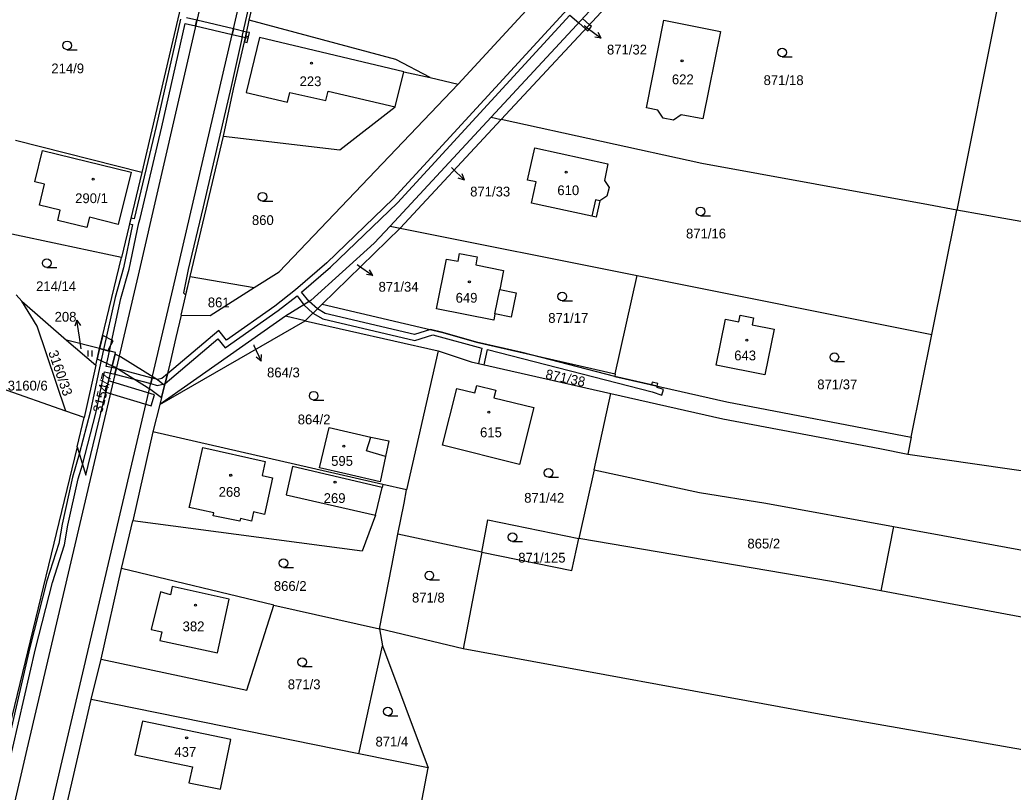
# Model space of a CAD drawing. Extents: x -776734 to -748832, y -1118122 to -976986.
# Drawn here: x -752855.4 to -752682.9, y -1114956.2 to -1114822 of the extents above; entities that cross this region are included whole.
import ezdxf

# ---------------------------------------------------------------- set-up
doc = ezdxf.new("R2010")
doc.units = 0
for name, color, linetype in [('KM_Hranice parcel', 7, 'Continuous'), ('KM_Parcelní čísla', 7, 'Continuous'), ('KM_Pop  PČ popisy', 7, 'Continuous'), ('KM_Vnitřní kresba', 7, 'Continuous'), ('KM_Věcná břemena k části', 7, 'Continuous'), ('KM_Značky budov', 7, 'Continuous'), ('KM_Značky kultur', 7, 'Continuous')]:
    doc.layers.add(name, color=color, linetype=linetype)

msp = doc.modelspace()

# ---------------------------------------------------------------- linework, layer by layer
at = {"layer": 'KM_Hranice parcel'}
for p, q in [((-752815.59, -1114822.06), (-752810.36, -1114800.13)), ((-752743.15, -1114806.14), (-752773.56, -1114838.95)), ((-752741.43, -1114806.72), (-752771.79, -1114839.34)), ((-752826.26, -1114814.37), (-752834.25, -1114848.56)), ((-752779.3, -1114833.2), (-752760.8, -1114813.12)), ((-752685.29, -1114818.2), (-752692.66, -1114855.09)), ((-752810.37, -1114865.82), (-752779.3, -1114833.2)), ((-752784.17, -1114832.03), (-752779.3, -1114833.2)), ((-752773.56, -1114838.95), (-752791.09, -1114857.86)), ((-752771.79, -1114839.34), (-752789.34, -1114858.2)), ((-752773.56, -1114838.95), (-752771.79, -1114839.34)), ((-752834.25, -1114848.56), (-752856.18, -1114842.98)), ((-752825.84, -1114866.6), (-752820.07, -1114842.27)), ((-752834.25, -1114848.56), (-752837.78, -1114863.34)), ((-752697, -1114876.69), (-752692.66, -1114855.09)), ((-752646.6, -1114863.22), (-752692.66, -1114855.09)), ((-752789.34, -1114858.2), (-752802.89, -1114871.42)), ((-752791.09, -1114857.86), (-752789.34, -1114858.2)), ((-752789.34, -1114858.2), (-752748.21, -1114866.44)), ((-752841.58, -1114879.15), (-752837.78, -1114863.34)), ((-752814.71, -1114868.55), (-752810.37, -1114865.82)), ((-752827.44, -1114873.35), (-752825.84, -1114866.6)), ((-752825.84, -1114866.6), (-752814.71, -1114868.55)), ((-752751.98, -1114883.52), (-752748.21, -1114866.44)), ((-752748.21, -1114866.44), (-752697, -1114876.69)), ((-752856.07, -1114869.8), (-752855.1, -1114870.94)), ((-752855.1, -1114870.94), (-752847.34, -1114877.68)), ((-752809.29, -1114873.54), (-752831.11, -1114888.85)), ((-752831.11, -1114888.85), (-752805.86, -1114874.32)), ((-752805.86, -1114874.32), (-752809.29, -1114873.54)), ((-752805.86, -1114874.32), (-752782.75, -1114879.56)), ((-752847.34, -1114877.68), (-752842.23, -1114882.06)), ((-752841.58, -1114879.15), (-752847.34, -1114877.68)), ((-752700.55, -1114894.54), (-752697, -1114876.69)), ((-752842.23, -1114882.06), (-752841.58, -1114879.15)), ((-752782.75, -1114879.56), (-752788.24, -1114903.71)), ((-752782.75, -1114879.56), (-752777.02, -1114881.46)), ((-752777.02, -1114881.46), (-752752.74, -1114886.95)), ((-752842.23, -1114882.06), (-752844.28, -1114891.15)), ((-752847.45, -1114890.03), (-752858.6, -1114886.11)), ((-752755.67, -1114900.22), (-752752.74, -1114886.95)), ((-752844.28, -1114891.15), (-752847.45, -1114890.03)), ((-752831.11, -1114888.85), (-752832.34, -1114893.61)), ((-752845.51, -1114896.23), (-752844.28, -1114891.15)), ((-752832.34, -1114893.61), (-752835.83, -1114909.11)), ((-752792.39, -1114902.76), (-752832.34, -1114893.61)), ((-752700.55, -1114894.54), (-752701.14, -1114897.48)), ((-752845.51, -1114896.23), (-752858.15, -1114948.58)), ((-752755.67, -1114900.22), (-752758.3, -1114912.14)), ((-752793.64, -1114908.09), (-752792.51, -1114903.31)), ((-752792.39, -1114902.76), (-752792.51, -1114903.31)), ((-752788.24, -1114903.71), (-752792.39, -1114902.76)), ((-752788.68, -1114905.99), (-752788.24, -1114903.71)), ((-752789.74, -1114911.43), (-752788.68, -1114905.99)), ((-752725.83, -1114905.99), (-752703.64, -1114910.05)), ((-752837.8, -1114917.4), (-752835.83, -1114909.11)), ((-752703.64, -1114910.05), (-752705.87, -1114921.23)), ((-752703.64, -1114910.05), (-752695.08, -1114911.61)), ((-752790.8, -1114916.88), (-752789.74, -1114911.43)), ((-752775.2, -1114914.55), (-752789.74, -1114911.43)), ((-752714.41, -1114919.62), (-752758.3, -1114912.14)), ((-752841.33, -1114933.1), (-752837.8, -1114917.4)), ((-752811.3, -1114923.77), (-752837.8, -1114917.4)), ((-752792.93, -1114927.88), (-752790.8, -1114916.88)), ((-752705.87, -1114921.23), (-752714.41, -1114919.62)), ((-752625.35, -1114936.43), (-752705.87, -1114921.23)), ((-752811.3, -1114923.77), (-752792.93, -1114927.88)), ((-752778.39, -1114931.34), (-752792.93, -1114927.88)), ((-752792.93, -1114927.88), (-752792.43, -1114930.79)), ((-752796.52, -1114949.56), (-752792.43, -1114930.79)), ((-752792.43, -1114930.79), (-752784.52, -1114951.99)), ((-752843.05, -1114940.12), (-752841.33, -1114933.1)), ((-752848.45, -1114963.61), (-752843.05, -1114940.12)), ((-752796.52, -1114949.56), (-752843.05, -1114940.12)), ((-752784.52, -1114951.99), (-752796.52, -1114949.56)), ((-752787.01, -1114965.1), (-752784.52, -1114951.99))]:
    msp.add_line(p, q, dxfattribs=at)
for points in [[(-752785.56, -1114653.59), (-752802.93, -1114729.01), (-752805.4, -1114739.76), (-752817.12, -1114789.2), (-752834.89, -1114866.39), (-752854.22, -1114948.74), (-752882.92, -1115072.56), (-752893.17, -1115116.65), (-752898.67, -1115140.84), (-752901.21, -1115152.69), (-752902.77, -1115162.03), (-752904.54, -1115175.28), (-752905.59, -1115186.25), (-752907.24, -1115206.15), (-752907.97, -1115217.91), (-752910.76, -1115260.79), (-752912.73, -1115288.36)], [(-752893.27, -1115146.65), (-752892.2, -1115141.48), (-752884.4, -1115107.23), (-752882.98, -1115101.01), (-752882.52, -1115099.06), (-752878.08, -1115079.92), (-752848.33, -1114951.79), (-752828.79, -1114868.65), (-752810.45, -1114789.66), (-752799.15, -1114740.86), (-752796.77, -1114730.63), (-752779.02, -1114654.54)], [(-752820.07, -1114842.27), (-752818.33, -1114834.09), (-752816.08, -1114824.33), (-752815.59, -1114822.06)], [(-752784.17, -1114832.03), (-752790.14, -1114828.93), (-752815.59, -1114822.06)], [(-752746.57, -1114837.3), (-752743.53, -1114822.09), (-752733.73, -1114824.05), (-752736.77, -1114839.24), (-752740.53, -1114838.52), (-752741.89, -1114839.44), (-752743.68, -1114839.12), (-752744.59, -1114837.72), (-752746.57, -1114837.3)], [(-752820.07, -1114842.27), (-752799.84, -1114844.62), (-752790.23, -1114837.17), (-752788.71, -1114831.09), (-752784.17, -1114832.03)], [(-752692.66, -1114855.09), (-752697.57, -1114854.2), (-752736.92, -1114847), (-752771.79, -1114839.34)], [(-752766.54, -1114853.86), (-752765.74, -1114850.2), (-752767.21, -1114849.89), (-752765.97, -1114844.25), (-752753.28, -1114847.03), (-752753.88, -1114849.93), (-752753.07, -1114851.16), (-752753.43, -1114852.65), (-752754.68, -1114853.45), (-752755.3, -1114856.31), (-752756.05, -1114856.15), (-752766.54, -1114853.86)], [(-752837.78, -1114863.34), (-752862.35, -1114858.12), (-752867.05, -1114856.95)], [(-752791.09, -1114857.86), (-752793.86, -1114860.85), (-752804.88, -1114870.79), (-752809.29, -1114873.54)], [(-752776.24, -1114864.59), (-752771.39, -1114865.56), (-752772.05, -1114868.89), (-752769.23, -1114869.45), (-752770.06, -1114873.67), (-752772.89, -1114873.12), (-752773.1, -1114874.19), (-752783.04, -1114872.22), (-752781.3, -1114863.59), (-752779.3, -1114863.99), (-752779.03, -1114862.63), (-752775.97, -1114863.22), (-752776.24, -1114864.59)], [(-752827.44, -1114873.35), (-752822.39, -1114873.42), (-752814.71, -1114868.55)], [(-752847.45, -1114890.03), (-752852.42, -1114875.24), (-752855.1, -1114870.94)], [(-752802.89, -1114871.42), (-752803.31, -1114871.83), (-752805.86, -1114874.32)], [(-752802.89, -1114871.42), (-752781.94, -1114876.34), (-752776.11, -1114878.05), (-752751.98, -1114883.52)], [(-752827.44, -1114873.35), (-752828.35, -1114877.2), (-752829.37, -1114881.83), (-752830.82, -1114887.64), (-752831.11, -1114888.85)], [(-752728.19, -1114875), (-752724.39, -1114875.76), (-752725.98, -1114883.74), (-752734.46, -1114882.04), (-752732.86, -1114874.06), (-752730.51, -1114874.53), (-752730.27, -1114873.34), (-752727.95, -1114873.8), (-752728.19, -1114875)], [(-752845.51, -1114896.23), (-752843.96, -1114901.18), (-752838.83, -1114879.85), (-752841.58, -1114879.15)], [(-752751.98, -1114883.52), (-752752.09, -1114884.01), (-752732.61, -1114888.43), (-752700.55, -1114894.54)], [(-752776.02, -1114885.55), (-752772.74, -1114886.37), (-752773.06, -1114887.69), (-752766.16, -1114889.41), (-752768.62, -1114899.28), (-752782, -1114895.92), (-752779.54, -1114886.07), (-752776.36, -1114886.87), (-752776.02, -1114885.55)], [(-752752.74, -1114886.95), (-752733.28, -1114891.34), (-752706.04, -1114896.53), (-752701.14, -1114897.48)], [(-752791.93, -1114897.91), (-752792.83, -1114902.29), (-752798.82, -1114900.9), (-752803.38, -1114899.85), (-752801.71, -1114892.88), (-752794.45, -1114894.53), (-752791.32, -1114895.19), (-752791.93, -1114897.91)], [(-752701.14, -1114897.48), (-752677.47, -1114900.93), (-752628.16, -1114910.57), (-752560.85, -1114923), (-752495.15, -1114935.68)], [(-752792.51, -1114903.31), (-752808.08, -1114899.66), (-752809.18, -1114904.57), (-752793.64, -1114908.09)], [(-752755.67, -1114900.22), (-752737.36, -1114904.15), (-752725.83, -1114905.99)], [(-752793.64, -1114908.09), (-752795.95, -1114914.36), (-752835.83, -1114909.11)], [(-752775.2, -1114914.55), (-752774.13, -1114908.93), (-752758.3, -1114912.14)], [(-752775.2, -1114914.55), (-752759.53, -1114917.72), (-752758.3, -1114912.14)], [(-752695.08, -1114911.61), (-752645.11, -1114920.85), (-752614.18, -1114925.39), (-752589.45, -1114929.97), (-752559.78, -1114936.24), (-752492.82, -1114950.07)], [(-752775.2, -1114914.55), (-752776.27, -1114920.18), (-752778.39, -1114931.34)], [(-752841.33, -1114933.1), (-752815.99, -1114938.5), (-752811.3, -1114923.77)], [(-752475.59, -1114992.09), (-752527.74, -1114980.32), (-752559.98, -1114972.3), (-752612.44, -1114961.68), (-752676.94, -1114949.64), (-752717.21, -1114942.55), (-752778.39, -1114931.34)], [(-752826.07, -1114954.59), (-752820.56, -1114955.71), (-752818.8, -1114947.1), (-752834.13, -1114943.91), (-752835.45, -1114949.78), (-752825.47, -1114951.85), (-752826.07, -1114954.59)]]:
    msp.add_lwpolyline(points, dxfattribs=at)
at = {"layer": 'KM_Pop  PČ popisy'}
for p, q in [((-752757.4, -1114823.03), (-752756.85, -1114823.43)), ((-752756.85, -1114823.43), (-752754.422, -1114825.194)), ((-752754.422, -1114825.194), (-752754.938, -1114824.2)), ((-752754.422, -1114825.194), (-752755.527, -1114825.01)), ((-752780.45, -1114847.68), (-752780.35, -1114847.78)), ((-752780.35, -1114847.78), (-752778.191, -1114849.865)), ((-752778.191, -1114849.865), (-752778.564, -1114848.809)), ((-752778.191, -1114849.865), (-752779.26, -1114849.529)), ((-752796.83, -1114864.55), (-752796.59, -1114864.72)), ((-752796.59, -1114864.72), (-752794.132, -1114866.441)), ((-752794.132, -1114866.441), (-752794.665, -1114865.457)), ((-752794.132, -1114866.441), (-752795.239, -1114866.277)), ((-752845.549, -1114874.206), (-752845.887, -1114875.273)), ((-752845.08, -1114877.17), (-752845.549, -1114874.206)), ((-752845.549, -1114874.206), (-752844.898, -1114875.117)), ((-752844.77, -1114879.2), (-752845.08, -1114877.17)), ((-752814.81, -1114878.52), (-752814.77, -1114878.6)), ((-752814.77, -1114878.6), (-752813.502, -1114881.32)), ((-752813.502, -1114881.32), (-752814.379, -1114880.624)), ((-752813.502, -1114881.32), (-752813.471, -1114880.201))]:
    msp.add_line(p, q, dxfattribs=at)
at = {"layer": 'KM_Vnitřní kresba'}
for p, q in [((-752813.78, -1114825.1), (-752816.09, -1114834.64)), ((-752788.71, -1114831.09), (-752813.78, -1114825.1)), ((-752816.09, -1114834.64), (-752808.91, -1114836.33)), ((-752808.91, -1114836.33), (-752808.52, -1114834.66)), ((-752808.52, -1114834.66), (-752802.28, -1114836.07)), ((-752802.28, -1114836.07), (-752801.9, -1114834.4)), ((-752801.9, -1114834.4), (-752790.23, -1114837.17)), ((-752852.84, -1114850.16), (-752851.52, -1114844.71)), ((-752851.52, -1114844.71), (-752836.12, -1114848.49)), ((-752836.12, -1114848.49), (-752838.33, -1114857.58)), ((-752851.15, -1114850.58), (-752852.84, -1114850.16)), ((-752852.02, -1114854.23), (-752851.15, -1114850.58)), ((-752755.41, -1114853.29), (-752756.05, -1114856.15)), ((-752754.68, -1114853.45), (-752755.41, -1114853.29)), ((-752848.43, -1114855.1), (-752852.02, -1114854.23)), ((-752848.84, -1114856.88), (-752848.43, -1114855.1)), ((-752843.78, -1114858.1), (-752848.84, -1114856.88)), ((-752843.35, -1114856.32), (-752843.78, -1114858.1)), ((-752838.33, -1114857.58), (-752843.35, -1114856.32)), ((-752772.89, -1114873.12), (-752772.05, -1114868.89)), ((-752795.2, -1114896.91), (-752794.45, -1114894.53)), ((-752825.85, -1114906.13), (-752823.63, -1114896.34)), ((-752823.63, -1114896.34), (-752812.8, -1114898.8)), ((-752791.93, -1114897.91), (-752795.2, -1114896.91)), ((-752812.8, -1114898.8), (-752813.36, -1114901.21)), ((-752813.36, -1114901.21), (-752811.53, -1114901.63)), ((-752811.53, -1114901.63), (-752812.96, -1114907.98)), ((-752826, -1114906.77), (-752825.85, -1114906.13)), ((-752821.74, -1114907.7), (-752826, -1114906.77)), ((-752814.82, -1114907.55), (-752815.18, -1114909.12)), ((-752812.96, -1114907.98), (-752814.82, -1114907.55)), ((-752821.88, -1114908.2), (-752821.74, -1114907.7)), ((-752817.24, -1114909.15), (-752821.88, -1114908.2)), ((-752817.08, -1114908.71), (-752817.24, -1114909.15)), ((-752815.18, -1114909.12), (-752817.08, -1114908.71)), ((-752831.03, -1114921.42), (-752832.61, -1114927.97)), ((-752829.28, -1114921.92), (-752831.03, -1114921.42)), ((-752828.95, -1114920.48), (-752829.28, -1114921.92)), ((-752819.07, -1114922.68), (-752828.95, -1114920.48)), ((-752821.12, -1114932.04), (-752819.07, -1114922.68)), ((-752832.61, -1114927.97), (-752830.76, -1114928.4)), ((-752830.76, -1114928.4), (-752831.1, -1114929.86)), ((-752831.1, -1114929.86), (-752821.12, -1114932.04))]:
    msp.add_line(p, q, dxfattribs=at)
at = {"layer": 'KM_Věcná břemena k části'}
for points in [[(-752813.41, -1114809.62), (-752816.79, -1114824.68), (-752816.87, -1114825.25), (-752818.74, -1114833.62), (-752820.13, -1114839.6), (-752823.61, -1114854.53), (-752826.2, -1114865.43), (-752827.03, -1114869.46), (-752826.62, -1114869.87), (-752826.48, -1114869.3), (-752825.84, -1114866.6), (-752820.07, -1114842.27), (-752818.33, -1114834.09), (-752816.43, -1114825.84), (-752816.2, -1114824.87), (-752816.08, -1114824.33), (-752815.59, -1114822.06), (-752810.36, -1114800.13)], [(-752760.29, -1114820.18), (-752790.58, -1114853.11), (-752802.12, -1114864.27), (-752807.54, -1114868.93), (-752811.13, -1114871.76), (-752819.56, -1114877.67), (-752820.88, -1114876), (-752829.8, -1114883.55), (-752830.21, -1114885.2), (-752821.02, -1114877.44), (-752819.76, -1114879.03), (-752810.53, -1114872.56), (-752807.28, -1114869.99), (-752806.11, -1114871.56), (-752804.52, -1114873.01), (-752802.8, -1114874.01), (-752786.83, -1114877.77), (-752783.66, -1114876.74), (-752775.15, -1114879.08), (-752775.76, -1114881.75), (-752774.79, -1114881.96), (-752774.18, -1114879.34), (-752745.6, -1114886.69), (-752743.92, -1114887.23), (-752743.61, -1114886.28), (-752744.73, -1114885.92), (-752744.68, -1114885.69), (-752745.67, -1114885.47), (-752752.09, -1114884.01), (-752768.19, -1114879.85), (-752776.11, -1114878.05), (-752781.94, -1114876.34), (-752784.1, -1114875.83), (-752786.87, -1114876.73), (-752802.41, -1114873.07), (-752803.73, -1114872.24), (-752805.17, -1114870.97), (-752806.52, -1114869.36), (-752801.45, -1114865.01), (-752789.85, -1114853.8), (-752759.86, -1114821.19), (-752758.34, -1114822.53), (-752757.14, -1114823.6), (-752756.46, -1114822.87), (-752757.66, -1114821.8)], [(-752859.67, -1114961.34), (-752852.75, -1114931.34), (-752849.79, -1114919.81), (-752847.69, -1114913.27), (-752847.1, -1114909.84), (-752845.3, -1114901.77), (-752844.54, -1114899.34), (-752842.25, -1114890.4), (-752840.73, -1114883.21), (-752839.69, -1114883.43), (-752838.93, -1114883.61), (-752838.7, -1114882.61), (-752839.45, -1114882.43), (-752840.45, -1114882.25), (-752839.87, -1114879.59), (-752837.89, -1114870.47), (-752836.47, -1114865.35), (-752834.78, -1114857.29), (-752834.55, -1114856.57), (-752830.76, -1114840.64), (-752826.69, -1114822.66), (-752824.92, -1114823.08), (-752824.69, -1114822.1), (-752826.48, -1114821.68)], [(-752827.53, -1114821.89), (-752831.78, -1114840.57), (-752835.6, -1114856.59), (-752836.15, -1114856.5), (-752836.38, -1114857.48), (-752835.85, -1114857.57), (-752837.44, -1114865.11), (-752838.87, -1114870.25), (-752840.89, -1114879.33), (-752841.6, -1114882.52), (-752843.23, -1114890.19), (-752845.12, -1114897.49), (-752846.27, -1114901.51), (-752848.09, -1114909.66), (-752848.67, -1114913.04), (-752850.75, -1114919.53)], [(-752850.75, -1114919.53), (-752853.72, -1114931.09), (-752860.63, -1114961.05), (-752862.31, -1114967.67), (-752866.41, -1114987.03), (-752868.12, -1114993.44), (-752874.14, -1115020.02), (-752874.34, -1115021.57), (-752877.16, -1115034.56), (-752877.36, -1115036.4), (-752880.61, -1115050.43)]]:
    msp.add_lwpolyline(points, dxfattribs=at)
for points in [[(-752818.33, -1114823.6), (-752824.69, -1114822.1), (-752824.92, -1114823.08), (-752818.56, -1114824.58)], [(-752756.46, -1114822.87), (-752757.14, -1114823.6), (-752756.77, -1114823.93), (-752756.09, -1114823.2)], [(-752816.26, -1114825.12), (-752816.04, -1114824.14), (-752818.33, -1114823.6), (-752818.56, -1114824.58)], [(-752816.04, -1114824.14), (-752816.26, -1114825.12), (-752815.78, -1114825.23), (-752815.55, -1114824.25)], [(-752816.43, -1114825.84), (-752815.94, -1114825.95), (-752815.72, -1114824.98), (-752816.2, -1114824.87)], [(-752839.91, -1114879.58), (-752839.96, -1114879.18), (-752839.23, -1114877.79), (-752841.03, -1114876.87), (-752841.58, -1114879.15)], [(-752839.38, -1114882.13), (-752838.9, -1114880.15), (-752838.83, -1114879.85), (-752839.91, -1114879.58), (-752841.58, -1114879.15), (-752841.98, -1114880.94)], [(-752837.98, -1114880.57), (-752838.9, -1114880.15), (-752839.38, -1114882.13), (-752838.93, -1114882.34), (-752832.67, -1114886.24), (-752830.82, -1114887.64), (-752830.3, -1114885.55), (-752831.53, -1114884.6)], [(-752832.46, -1114884.28), (-752838.7, -1114882.61), (-752838.93, -1114883.61), (-752832.69, -1114885.25)], [(-752840.01, -1114884.75), (-752840.48, -1114886.7), (-752832.64, -1114889.13), (-752832.05, -1114887.22)], [(-752830.21, -1114885.2), (-752829.8, -1114883.55), (-752830.76, -1114884.36), (-752831.54, -1114884.53), (-752832.46, -1114884.28), (-752832.69, -1114885.25), (-752831.56, -1114885.55), (-752830.3, -1114885.28)], [(-752745.67, -1114885.47), (-752744.68, -1114885.69), (-752744.57, -1114885.2), (-752745.56, -1114884.98)]]:
    msp.add_lwpolyline(points, close=True, dxfattribs=at)
at = {"layer": 'KM_Značky budov'}
for centre in [(-752804.7868, -1114829.5492), (-752740.3868, -1114829.1692), (-752760.5168, -1114848.5092), (-752842.7168, -1114849.7192), (-752777.3368, -1114867.5592), (-752729.1268, -1114877.6992), (-752773.9768, -1114890.2192), (-752799.1468, -1114896.1192), (-752818.8068, -1114901.1792), (-752800.6768, -1114902.3892), (-752824.9168, -1114923.7292), (-752826.4568, -1114946.7892)]:
    msp.add_circle(centre, 0.175, dxfattribs=at)
at = {"layer": 'KM_Značky kultur'}
for p, q in [((-752847.223, -1114827.21), (-752845.473, -1114827.21)), ((-752722.983, -1114828.44), (-752721.233, -1114828.44)), ((-752813.263, -1114853.51), (-752811.513, -1114853.51)), ((-752737.163, -1114856.06), (-752735.413, -1114856.06)), ((-752850.773, -1114865.05), (-752849.023, -1114865.05)), ((-752761.193, -1114870.86), (-752759.443, -1114870.86)), ((-752843.578, -1114880.51), (-752843.578, -1114879.46)), ((-752842.877, -1114880.51), (-752842.877, -1114879.46)), ((-752713.923, -1114881.38), (-752712.173, -1114881.38)), ((-752804.393, -1114888.09), (-752802.643, -1114888.09)), ((-752763.583, -1114901.52), (-752761.833, -1114901.52)), ((-752769.863, -1114912.68), (-752768.113, -1114912.68)), ((-752809.623, -1114917.2), (-752807.873, -1114917.2)), ((-752784.293, -1114919.34), (-752782.543, -1114919.34)), ((-752806.373, -1114934.41), (-752804.623, -1114934.41)), ((-752791.513, -1114942.99), (-752789.763, -1114942.99))]:
    msp.add_line(p, q, dxfattribs=at)
for centre in [(-752847.2229, -1114826.4598), (-752722.9829, -1114827.6898), (-752813.2629, -1114852.7598), (-752737.1629, -1114855.3098), (-752850.7729, -1114864.2998), (-752761.1929, -1114870.1098), (-752713.9229, -1114880.6298), (-752804.3929, -1114887.3398), (-752763.5829, -1114900.7698), (-752769.8629, -1114911.9298), (-752809.6229, -1114916.4498), (-752784.2929, -1114918.5898), (-752806.3729, -1114933.6598), (-752791.5129, -1114942.2398)]:
    msp.add_circle(centre, 0.75, dxfattribs=at)

# ---------------------------------------------------------------- texts
at = {"layer": 'KM_Parcelní čísla'}
for s, p in [('871/32', (-752753.43, -1114828.048)), ('214/9', (-752849.97, -1114831.32)), ('622', (-752742.15, -1114833.22)), ('871/18', (-752726.22, -1114833.36)), ('223', (-752806.84, -1114833.55)), ('290/1', (-752845.83, -1114853.88)), ('871/33', (-752777.2, -1114852.718)), ('610', (-752762.05, -1114852.49)), ('860', (-752815.12, -1114857.68)), ('871/16', (-752739.7, -1114860.01)), ('214/14', (-752852.62, -1114869.17)), ('871/34', (-752793.12, -1114869.268)), ('649', (-752779.725, -1114871.18)), ('861', (-752822.78, -1114871.98)), ('208', (-752849.4, -1114874.48)), ('871/17', (-752763.63, -1114874.68)), ('643', (-752731.32, -1114881.2)), ('864/3', (-752812.49, -1114884.158)), ('3160/6', (-752857.55, -1114886.44)), ('871/37', (-752716.89, -1114886.23)), ('864/2', (-752807.16, -1114892.32)), ('615', (-752775.48, -1114894.56)), ('595', (-752801.355, -1114899.53)), ('268', (-752820.9, -1114904.91)), ('871/42', (-752767.81, -1114905.94)), ('269', (-752802.65, -1114905.99)), ('865/2', (-752729.028, -1114913.89)), ('871/125', (-752768.846, -1114916.34)), ('866/2', (-752811.31, -1114921.26)), ('871/8', (-752787.31, -1114923.28)), ('382', (-752827.16, -1114928.28)), ('871/3', (-752808.89, -1114938.35)), ('871/4', (-752793.65, -1114948.3)), ('437', (-752828.59, -1114950.1))]:
    msp.add_text(s, height=1.7, dxfattribs=at).set_placement(p)
for s, rotation, p in [('3160/33', 289, (-752850.523, -1114879.786)), ('3154/7', 76, (-752841.145, -1114890.445)), ('871/38', 348, (-752764.216, -1114884.371))]:
    msp.add_text(s, height=1.7, rotation=rotation, dxfattribs=at).set_placement(p)

doc.saveas('drawing.dxf')
